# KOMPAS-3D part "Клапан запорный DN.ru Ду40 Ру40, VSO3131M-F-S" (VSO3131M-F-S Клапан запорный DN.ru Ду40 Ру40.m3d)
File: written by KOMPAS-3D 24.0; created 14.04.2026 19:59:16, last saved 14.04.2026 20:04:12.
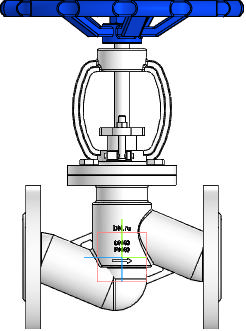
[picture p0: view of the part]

Document properties: Автор: R2D2; Полное имя файла: VSO3131M-F-S Клапан запорный DN.ru Ду40 Ру40.cdw

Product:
- Part/product: Клапан запорный DN.ru Ду40 Ру40  | designation VSO3131M-F-S
    Масса: 9.54
    Раздел спецификации: Прочие изделия
    Форматы листов документа: A2
    Примечание: D090-02141

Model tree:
1. Операция без истории:3

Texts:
  VSO3131M-F-S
